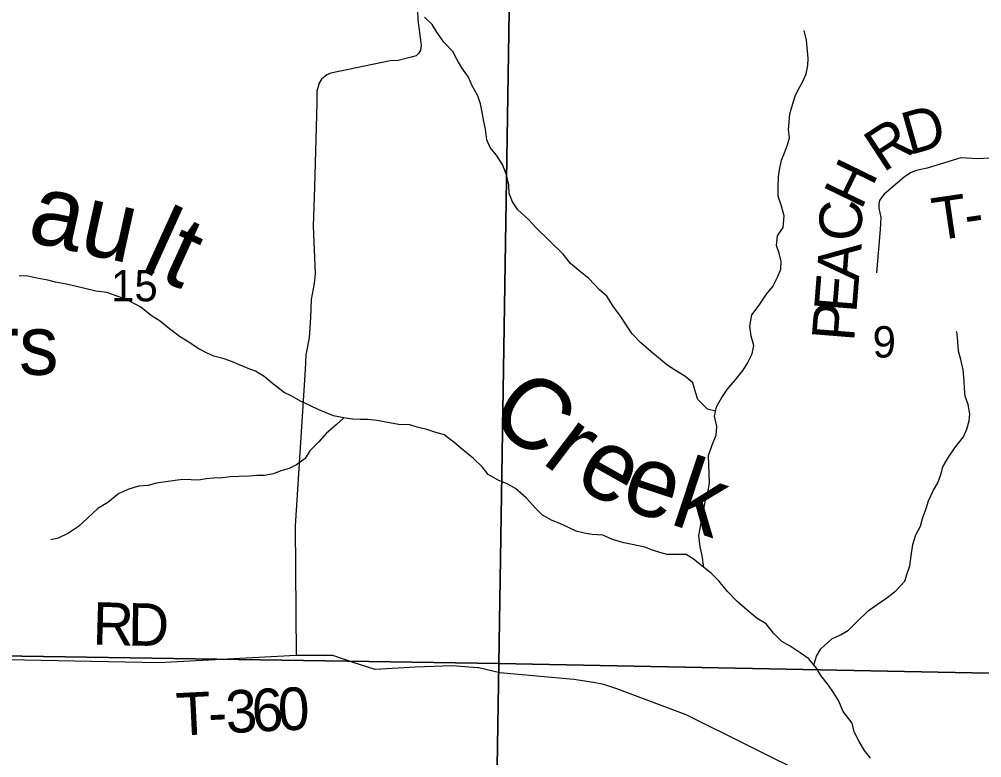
# Model space of a CAD drawing. Extents: x -3.6 to 34, y 0 to 32.8.
# Drawn here: x -2.413 to -1.128, y 31.007 to 31.993 of the extents above; entities that cross this region are included whole.
import ezdxf

# ---------------------------------------------------------------- set-up
doc = ezdxf.new("R2010")
doc.units = 0
for name, color, linetype in [('GM_X_Corporation', 7, 'Continuous'), ('GM_X_Minor_River', 7, 'Continuous'), ('GM_X_Minor_River_Text', 7, 'Continuous'), ('GM_X_Section_Text', 7, 'Continuous'), ('GM_X_Township_Road', 7, 'Continuous'), ('GM_X_Township_Road_Text', 7, 'Continuous'), ('GM_X_Unincorporated_Text', 7, 'Continuous')]:
    doc.layers.add(name, color=color, linetype=linetype)

msp = doc.modelspace()

# ---------------------------------------------------------------- linework, layer by layer
at = {"layer": 'GM_X_Corporation'}
for points in [[(-2.7692, 32.1629), (-1.7561, 32.1438), (-1.7722, 31.1326), (-2.786, 31.1483)], [(-1.7561, 32.1438), (-0.7385, 32.1141), (-0.7569, 31.1125), (-1.7722, 31.1326)], [(-1.7722, 31.1326), (-1.7886, 30.1145), (-2.8032, 30.1329), (-2.786, 31.1483)], [(-1.7722, 31.1326), (-0.7569, 31.1125), (-0.7755, 30.0957), (-1.7886, 30.1145)]]:
    msp.add_lwpolyline(points, close=True, dxfattribs=at)
at = {"layer": 'GM_X_Minor_River'}
for points in [[(-1.4828, 31.4696), (-1.4939, 31.4723), (-1.5066, 31.485), (-1.5097, 31.4949), (-1.5133, 31.5073), (-1.5241, 31.5163), (-1.5378, 31.5248), (-1.5481, 31.5315), (-1.5592, 31.5408), (-1.5696, 31.5494), (-1.5826, 31.5606), (-1.5941, 31.5726), (-1.6034, 31.5861), (-1.6096, 31.5959), (-1.6192, 31.6086), (-1.6282, 31.6229), (-1.6381, 31.6315), (-1.652, 31.6465), (-1.6654, 31.6573), (-1.6768, 31.6666), (-1.6865, 31.679), (-1.7226, 31.7141), (-1.7326, 31.7253), (-1.7468, 31.7384), (-1.7541, 31.7489), (-1.7584, 31.7603), (-1.759, 31.7716), (-1.7622, 31.7849), (-1.7673, 31.7988), (-1.7758, 31.8116), (-1.7839, 31.8213), (-1.7882, 31.8319), (-1.79, 31.8459), (-1.7924, 31.8561), (-1.7945, 31.8686), (-1.7969, 31.8799), (-1.8005, 31.8905), (-1.8082, 31.9048), (-1.8129, 31.9154), (-1.8218, 31.9278), (-1.828, 31.9387), (-1.8339, 31.9496), (-1.8458, 31.9623), (-1.8551, 31.9755), (-1.8613, 31.9856), (-1.8716, 31.9953)], [(-1.4985, 31.2607), (-1.5008, 31.2769), (-1.5037, 31.2886), (-1.5054, 31.3034), (-1.5022, 31.3201), (-1.4998, 31.3312), (-1.4984, 31.3414), (-1.4959, 31.3528), (-1.4927, 31.3631), (-1.4909, 31.3734), (-1.4915, 31.3863), (-1.492, 31.398), (-1.4926, 31.4105), (-1.4879, 31.4231), (-1.482, 31.4376), (-1.4814, 31.449), (-1.4843, 31.463), (-1.4815, 31.4755), (-1.4748, 31.4878), (-1.4674, 31.4985), (-1.457, 31.5108), (-1.4462, 31.5242), (-1.4403, 31.5337), (-1.4341, 31.546), (-1.432, 31.5574), (-1.4356, 31.5695), (-1.4373, 31.5831), (-1.4345, 31.5983), (-1.4248, 31.6109), (-1.4148, 31.6255), (-1.4067, 31.6358), (-1.4, 31.6492), (-1.3957, 31.6591), (-1.3954, 31.6694), (-1.3982, 31.6803), (-1.4018, 31.6909), (-1.4001, 31.7038), (-1.3927, 31.7145), (-1.3914, 31.7301), (-1.395, 31.7433), (-1.3994, 31.7565), (-1.3992, 31.7683), (-1.399, 31.7823), (-1.3976, 31.7918), (-1.3948, 31.8048), (-1.3911, 31.8143), (-1.3868, 31.825), (-1.3842, 31.8345), (-1.3855, 31.8451), (-1.3849, 31.8553), (-1.3836, 31.8664), (-1.3804, 31.8785), (-1.3767, 31.89), (-1.3723, 31.8995), (-1.3664, 31.9098), (-1.3621, 31.9197), (-1.3599, 31.9308), (-1.3593, 31.9403), (-1.3602, 31.9505), (-1.3616, 31.9649), (-1.3648, 31.9777)], [(-1.3124, 31.0685), (-1.319, 31.0834), (-1.3253, 31.0939), (-1.3322, 31.1037), (-1.3426, 31.1168), (-1.3484, 31.1266), (-1.3585, 31.139), (-1.3699, 31.1468), (-1.3833, 31.1557), (-1.3944, 31.162), (-1.4055, 31.1732), (-1.4155, 31.1856), (-1.4274, 31.193), (-1.4407, 31.2038), (-1.4546, 31.2161), (-1.4672, 31.2288), (-1.4784, 31.2431), (-1.4884, 31.2528), (-1.5014, 31.2629), (-1.5129, 31.2726), (-1.5224, 31.2781), (-1.5349, 31.278), (-1.5478, 31.2782), (-1.5573, 31.2811), (-1.5672, 31.284), (-1.5774, 31.288), (-1.5919, 31.2912), (-1.6055, 31.2937), (-1.6207, 31.2984), (-1.6333, 31.3039), (-1.6477, 31.3048), (-1.6583, 31.3066), (-1.6693, 31.3095), (-1.6792, 31.3143), (-1.6918, 31.3201), (-1.7013, 31.3234), (-1.7139, 31.3305), (-1.7235, 31.3402), (-1.7358, 31.354), (-1.7503, 31.3664), (-1.761, 31.3727), (-1.7732, 31.3774), (-1.7866, 31.3852), (-1.7943, 31.3949), (-1.8062, 31.4065), (-1.8203, 31.4181), (-1.8322, 31.4282), (-1.8452, 31.4378), (-1.8589, 31.4418), (-1.8684, 31.4451), (-1.8813, 31.4483), (-1.8912, 31.4512), (-1.9063, 31.4518), (-1.9185, 31.4539), (-1.9348, 31.4571), (-1.9473, 31.4584), (-1.9575, 31.4583), (-1.9677, 31.4589), (-1.9772, 31.4603), (-1.9931, 31.4635), (-2.003, 31.4671), (-2.0125, 31.4712), (-2.0247, 31.4771), (-2.0373, 31.4829), (-2.0488, 31.4896), (-2.059, 31.4944), (-2.0721, 31.5048), (-2.0858, 31.5156), (-2.0973, 31.5231), (-2.1068, 31.5263), (-2.1175, 31.5311), (-2.1281, 31.5355), (-2.1391, 31.5392), (-2.1528, 31.5428), (-2.1627, 31.5472), (-2.173, 31.5527), (-2.1883, 31.5628), (-2.1986, 31.5694), (-2.2143, 31.5814), (-2.2246, 31.5899), (-2.2361, 31.597), (-2.2502, 31.6082), (-2.2636, 31.6156), (-2.2731, 31.62), (-2.2834, 31.6236), (-2.2956, 31.628), (-2.3103, 31.6297), (-2.3251, 31.6333), (-2.3362, 31.6358), (-2.3494, 31.639), (-2.3642, 31.6418), (-2.3745, 31.6444), (-2.3893, 31.6472), (-2.401, 31.6497), (-2.4128, 31.6503)], [(-1.3516, 31.1305), (-1.3483, 31.1425), (-1.3424, 31.1521), (-1.3278, 31.1656), (-1.3162, 31.171), (-1.3057, 31.1773), (-1.2941, 31.1888), (-1.2792, 31.203), (-1.2687, 31.2108), (-1.2545, 31.2204), (-1.2425, 31.2297), (-1.2302, 31.2428), (-1.227, 31.2527), (-1.2237, 31.2633), (-1.222, 31.2766), (-1.2196, 31.2915), (-1.2156, 31.3044), (-1.2094, 31.3159), (-1.2065, 31.3262), (-1.2018, 31.3395), (-1.1985, 31.3498), (-1.1919, 31.3643), (-1.186, 31.3738), (-1.1824, 31.3849), (-1.1795, 31.3952), (-1.1721, 31.4082), (-1.1633, 31.4204), (-1.1521, 31.4354), (-1.1477, 31.4457), (-1.1445, 31.4567), (-1.1435, 31.4662), (-1.1456, 31.4783), (-1.1499, 31.4896), (-1.1508, 31.4999), (-1.151, 31.5097), (-1.1523, 31.5245), (-1.1555, 31.5385), (-1.1584, 31.5498), (-1.1597, 31.5627), (-1.161, 31.5759)], [(-1.9794, 31.4607), (-1.9895, 31.4514), (-2.003, 31.4398), (-2.0127, 31.4287), (-2.0246, 31.4168), (-2.0309, 31.4064), (-2.0425, 31.3979), (-2.0522, 31.3929), (-2.0635, 31.3897), (-2.0733, 31.3857), (-2.0858, 31.3837), (-2.0956, 31.3835), (-2.1054, 31.383), (-2.1194, 31.3824), (-2.1308, 31.3819), (-2.1413, 31.3806), (-2.1527, 31.3801), (-2.1633, 31.3792), (-2.1731, 31.3775), (-2.1829, 31.3781), (-2.1946, 31.3784), (-2.2045, 31.3771), (-2.2169, 31.3754), (-2.2294, 31.3733), (-2.2407, 31.3705), (-2.2535, 31.3696), (-2.2663, 31.3656), (-2.2795, 31.3597), (-2.2944, 31.3478), (-2.3079, 31.3396), (-2.3214, 31.3269), (-2.3337, 31.3158), (-2.3468, 31.3065), (-2.3607, 31.2998), (-2.3705, 31.2978)], [(-1.2763, 31.0063), (-1.284, 31.0164), (-1.2914, 31.0284), (-1.2977, 31.0415), (-1.3006, 31.0532), (-1.3124, 31.0685)]]:
    msp.add_lwpolyline(points, dxfattribs=at)
at = {"layer": 'GM_X_Township_Road'}
for points in [[(-1.8808, 32.0045), (-1.8806, 31.992), (-1.876, 31.9575), (-1.8771, 31.9514), (-1.8794, 31.9471), (-1.8827, 31.9437), (-1.8894, 31.9421), (-1.9069, 31.9377), (-1.9172, 31.9372), (-1.9968, 31.9206), (-1.9985, 31.9199)], [(-1.9985, 31.9199), (-2.0018, 31.9183), (-2.0047, 31.9163), (-2.0089, 31.9125), (-2.0122, 31.9072), (-2.0155, 31.8969), (-2.0153, 31.8809), (-2.0185, 31.7684), (-2.0201, 31.7167), (-2.0174, 31.6533), (-2.0188, 31.64), (-2.0231, 31.6187), (-2.0239, 31.5944), (-2.0255, 31.5674), (-2.0298, 31.5446), (-2.0311, 31.5252), (-2.0441, 31.3165), (-2.0427, 31.1433)], [(-1.02, 31.8274), (-1.0323, 31.8223), (-1.0468, 31.8172), (-1.1082, 31.8076), (-1.1326, 31.8065), (-1.1556, 31.8076), (-1.2005, 31.7939), (-1.2153, 31.7907), (-1.2225, 31.7878), (-1.2311, 31.7821), (-1.2578, 31.759), (-1.2611, 31.7553), (-1.2642, 31.7506), (-1.2649, 31.7461), (-1.2648, 31.7407), (-1.2624, 31.7282), (-1.2633, 31.7122), (-1.2679, 31.654)], [(-1.9582, 31.1314), (-1.9654, 31.1338), (-1.9941, 31.1435), (-2.0427, 31.1433), (-2.2262, 31.1334), (-2.5183, 31.1393)], [(-1.7998, 31.127), (-1.8064, 31.1276), (-1.8345, 31.1298), (-1.884, 31.1278), (-1.9376, 31.1245), (-1.9582, 31.1314)], [(-1.1518, 30.8755), (-1.1536, 30.8762), (-1.1945, 30.8935), (-1.3548, 30.9811), (-1.5222, 31.0644), (-1.615, 31.0989), (-1.6323, 31.1049), (-1.6461, 31.1073), (-1.6721, 31.1113), (-1.7708, 31.1202), (-1.7989, 31.127), (-1.7998, 31.127)]]:
    msp.add_lwpolyline(points, dxfattribs=at)

# ---------------------------------------------------------------- texts
at = {"layer": 'GM_X_Minor_River_Text'}
for s, height, rotation, p in [('au', 0.09471, 347.5466, (-2.404, 31.697)), ('lt', 0.09471, 335.5492, (-2.2533, 31.6582)), ('Cr', 0.0947, 322.6978, (-1.7896, 31.4573)), ('e', 0.0947, 330.6968, (-1.6746, 31.3725)), ('ek', 0.09471, 341.6947, (-1.6131, 31.3417))]:
    msp.add_text(s, height=height, rotation=rotation, dxfattribs=at).set_placement(p)
at = {"layer": 'GM_X_Section_Text'}
for s, height, p in [('15', 0.04186, (-2.29, 31.6162)), ('9', 0.0419, (-1.2733, 31.5411))]:
    msp.add_text(s, height=height, rotation=0, dxfattribs=at).set_placement(p)
at = {"layer": 'GM_X_Township_Road_Text'}
for s, rotation, p in [('D', 15.8336, (-1.2242, 31.8111)), ('R', 33.1742, (-1.2591, 31.7874)), ('H', 64.0125, (-1.2889, 31.7369)), ('T', 8.2659, (-1.1894, 31.6971)), ('C', 89.8028, (-1.2875, 31.6968)), ('-', 8.2866, (-1.1473, 31.7032)), ('A', 85.4721, (-1.2917, 31.6423)), ('E', 85.4223, (-1.2951, 31.5998)), ('P', 85.4242, (-1.2981, 31.5616)), ('R', 358.419, (-2.3152, 31.158)), ('D', 359.2664, (-2.2677, 31.1566)), ('3', 2.8842, (-2.1359, 31.0396)), ('6', 2.8138, (-2.101, 31.0414)), ('0', 2.306, (-2.0662, 31.0431)), ('T', 2.9048, (-2.2017, 31.0363)), ('-', 2.9049, (-2.1592, 31.0384))]:
    msp.add_text(s, height=0.0568, rotation=rotation, dxfattribs=at).set_placement(p)
at = {"layer": 'GM_X_Unincorporated_Text'}
msp.add_text('Corners', height=0.07898, rotation=0, dxfattribs=at).set_placement((-2.7358, 31.5181))

doc.saveas('drawing.dxf')
